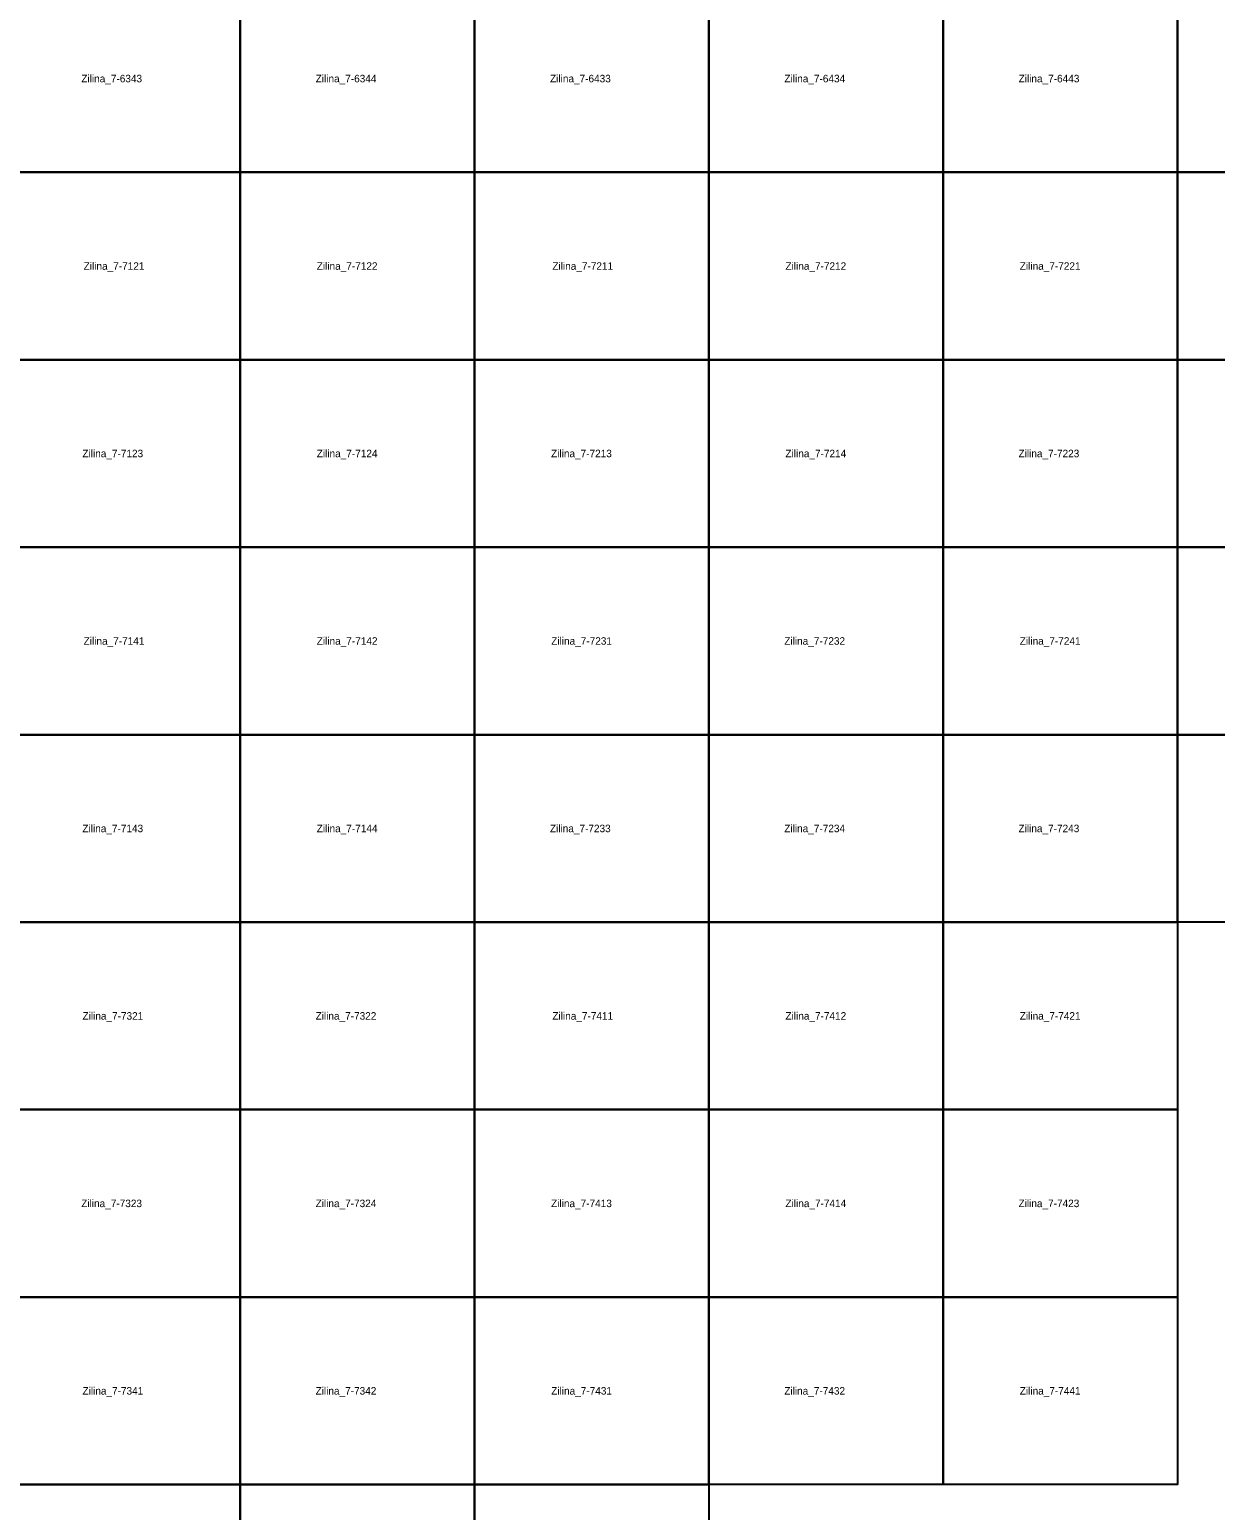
# Model space of a CAD drawing. Extents: x -445938 to -437812, y -1177250 to -1169500.
# Drawn here: x -444343 to -442762, y -1175784 to -1173810 of the extents above; entities that cross this region are included whole.
import ezdxf

# ---------------------------------------------------------------- set-up
doc = ezdxf.new("R2010")
doc.units = 0
for name, color, linetype in [('Vrstva 1', 7, 'Continuous'), ('Vrstva 4', 7, 'Continuous'), ('Vrstva 6', 7, 'Continuous')]:
    doc.layers.add(name, color=color, linetype=linetype)

msp = doc.modelspace()

# ---------------------------------------------------------------- linework, layer by layer
at = {"layer": 'Vrstva 1'}
msp.add_lwpolyline([(-440625, -1175500), (-441562.5, -1175500), (-441562.5, -1175000), (-442812.5, -1175000), (-442812.5, -1175750), (-443437.5, -1175750), (-443437.5, -1177250), (-445000, -1177250), (-445000, -1175500), (-445312.5, -1175500), (-445312.5, -1173750), (-445937.5, -1173750), (-445937.5, -1172250), (-445625, -1172250), (-445625, -1169500), (-444062.5, -1169500), (-444062.5, -1169750), (-441562.5, -1169750), (-441562.5, -1170000), (-440000, -1170000)], dxfattribs=at)
at = {"layer": 'Vrstva 4'}
for points in [[(-444062.5, -1173750), (-444062.5, -1174000), (-444375, -1174000), (-444375, -1173750)], [(-443750, -1173750), (-443750, -1174000), (-444062.5, -1174000), (-444062.5, -1173750)], [(-443437.5, -1173750), (-443437.5, -1174000), (-443750, -1174000), (-443750, -1173750)], [(-443125, -1173750), (-443125, -1174000), (-443437.5, -1174000), (-443437.5, -1173750)], [(-442812.5, -1173750), (-442812.5, -1174000), (-443125, -1174000), (-443125, -1173750)], [(-442500, -1173750), (-442500, -1174000), (-442812.5, -1174000), (-442812.5, -1173750)], [(-444062.5, -1174000), (-444062.5, -1174250), (-444375, -1174250), (-444375, -1174000)], [(-443750, -1174000), (-443750, -1174250), (-444062.5, -1174250), (-444062.5, -1174000)], [(-443437.5, -1174000), (-443437.5, -1174250), (-443750, -1174250), (-443750, -1174000)], [(-443125, -1174000), (-443125, -1174250), (-443437.5, -1174250), (-443437.5, -1174000)], [(-442812.5, -1174000), (-442812.5, -1174250), (-443125, -1174250), (-443125, -1174000)], [(-442500, -1174000), (-442500, -1174250), (-442812.5, -1174250), (-442812.5, -1174000)], [(-444062.5, -1174250), (-444062.5, -1174500), (-444375, -1174500), (-444375, -1174250)], [(-443750, -1174250), (-443750, -1174500), (-444062.5, -1174500), (-444062.5, -1174250)], [(-443437.5, -1174250), (-443437.5, -1174500), (-443750, -1174500), (-443750, -1174250)], [(-443125, -1174250), (-443125, -1174500), (-443437.5, -1174500), (-443437.5, -1174250)], [(-442812.5, -1174250), (-442812.5, -1174500), (-443125, -1174500), (-443125, -1174250)], [(-442500, -1174250), (-442500, -1174500), (-442812.5, -1174500), (-442812.5, -1174250)], [(-444062.5, -1174500), (-444062.5, -1174750), (-444375, -1174750), (-444375, -1174500)], [(-443750, -1174500), (-443750, -1174750), (-444062.5, -1174750), (-444062.5, -1174500)], [(-443437.5, -1174500), (-443437.5, -1174750), (-443750, -1174750), (-443750, -1174500)], [(-443125, -1174500), (-443125, -1174750), (-443437.5, -1174750), (-443437.5, -1174500)], [(-442812.5, -1174500), (-442812.5, -1174750), (-443125, -1174750), (-443125, -1174500)], [(-442500, -1174500), (-442500, -1174750), (-442812.5, -1174750), (-442812.5, -1174500)], [(-444062.5, -1174750), (-444062.5, -1175000), (-444375, -1175000), (-444375, -1174750)], [(-443750, -1174750), (-443750, -1175000), (-444062.5, -1175000), (-444062.5, -1174750)], [(-443437.5, -1174750), (-443437.5, -1175000), (-443750, -1175000), (-443750, -1174750)], [(-443125, -1174750), (-443125, -1175000), (-443437.5, -1175000), (-443437.5, -1174750)], [(-442812.5, -1174750), (-442812.5, -1175000), (-443125, -1175000), (-443125, -1174750)], [(-442500, -1174750), (-442500, -1175000), (-442812.5, -1175000), (-442812.5, -1174750)], [(-444062.5, -1175000), (-444062.5, -1175250), (-444375, -1175250), (-444375, -1175000)], [(-443750, -1175000), (-443750, -1175250), (-444062.5, -1175250), (-444062.5, -1175000)], [(-443437.5, -1175000), (-443437.5, -1175250), (-443750, -1175250), (-443750, -1175000)], [(-443125, -1175000), (-443125, -1175250), (-443437.5, -1175250), (-443437.5, -1175000)], [(-442812.5, -1175000), (-442812.5, -1175250), (-443125, -1175250), (-443125, -1175000)], [(-444062.5, -1175250), (-444062.5, -1175500), (-444375, -1175500), (-444375, -1175250)], [(-443750, -1175250), (-443750, -1175500), (-444062.5, -1175500), (-444062.5, -1175250)], [(-443437.5, -1175250), (-443437.5, -1175500), (-443750, -1175500), (-443750, -1175250)], [(-443125, -1175250), (-443125, -1175500), (-443437.5, -1175500), (-443437.5, -1175250)], [(-442812.5, -1175250), (-442812.5, -1175500), (-443125, -1175500), (-443125, -1175250)], [(-444062.5, -1175500), (-444062.5, -1175750), (-444375, -1175750), (-444375, -1175500)], [(-443750, -1175500), (-443750, -1175750), (-444062.5, -1175750), (-444062.5, -1175500)], [(-443437.5, -1175500), (-443437.5, -1175750), (-443750, -1175750), (-443750, -1175500)], [(-443125, -1175500), (-443125, -1175750), (-443437.5, -1175750), (-443437.5, -1175500)], [(-442812.5, -1175500), (-442812.5, -1175750), (-443125, -1175750), (-443125, -1175500)], [(-444062.5, -1175750), (-444062.5, -1176000), (-444375, -1176000), (-444375, -1175750)], [(-443750, -1175750), (-443750, -1176000), (-444062.5, -1176000), (-444062.5, -1175750)], [(-443437.5, -1175750), (-443437.5, -1176000), (-443750, -1176000), (-443750, -1175750)]]:
    msp.add_lwpolyline(points, close=True, dxfattribs=at)

# ---------------------------------------------------------------- texts
at = {"layer": 'Vrstva 6'}
for s, p in [('Zilina_7-6343', (-444274.296, -1173880)), ('Zilina_7-6344', (-443961.796, -1173880)), ('Zilina_7-6433', (-443649.296, -1173880)), ('Zilina_7-6434', (-443336.796, -1173880)), ('Zilina_7-6443', (-443024.454, -1173880)), ('Zilina_7-7121', (-444271.186, -1174130)), ('Zilina_7-7122', (-443960.379, -1174130)), ('Zilina_7-7211', (-443646.186, -1174130)), ('Zilina_7-7212', (-443335.379, -1174130)), ('Zilina_7-7221', (-443022.878, -1174130)), ('Zilina_7-7123', (-444272.879, -1174380)), ('Zilina_7-7124', (-443960.379, -1174380)), ('Zilina_7-7213', (-443647.879, -1174380)), ('Zilina_7-7214', (-443335.379, -1174380)), ('Zilina_7-7223', (-443024.572, -1174380)), ('Zilina_7-7141', (-444271.186, -1174630)), ('Zilina_7-7142', (-443960.379, -1174630)), ('Zilina_7-7231', (-443647.721, -1174630)), ('Zilina_7-7232', (-443336.914, -1174630)), ('Zilina_7-7241', (-443022.878, -1174630)), ('Zilina_7-7143', (-444272.879, -1174880)), ('Zilina_7-7144', (-443960.379, -1174880)), ('Zilina_7-7233', (-443649.414, -1174880)), ('Zilina_7-7234', (-443336.914, -1174880)), ('Zilina_7-7243', (-443024.572, -1174880)), ('Zilina_7-7321', (-444272.721, -1175130)), ('Zilina_7-7322', (-443961.914, -1175130)), ('Zilina_7-7411', (-443646.186, -1175130)), ('Zilina_7-7412', (-443335.379, -1175130)), ('Zilina_7-7421', (-443022.878, -1175130)), ('Zilina_7-7323', (-444274.414, -1175380)), ('Zilina_7-7324', (-443961.914, -1175380)), ('Zilina_7-7413', (-443647.879, -1175380)), ('Zilina_7-7414', (-443335.379, -1175380)), ('Zilina_7-7423', (-443024.572, -1175380)), ('Zilina_7-7341', (-444272.721, -1175630)), ('Zilina_7-7342', (-443961.914, -1175630)), ('Zilina_7-7431', (-443647.721, -1175630)), ('Zilina_7-7432', (-443336.914, -1175630)), ('Zilina_7-7441', (-443022.878, -1175630))]:
    msp.add_text(s, height=10, dxfattribs=at).set_placement(p)

doc.saveas('drawing.dxf')
